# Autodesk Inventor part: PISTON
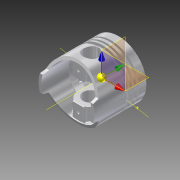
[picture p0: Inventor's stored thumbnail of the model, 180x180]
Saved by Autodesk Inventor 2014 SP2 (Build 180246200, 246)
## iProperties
Created: 2015-07
Part Number: PISTON
Material: Aluminio 6061
Document SubType Name: Modeling
Designer: Jaime
Density: 2.96864 g/cm^3
Appearance: Mecanizado - Aluminio
Mass: 440.2 g
Surface Area: 463.096 cm^2
Volume: 148.283 cm^3
Author: Jaime
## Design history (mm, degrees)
node "Plano_Lim_Superior"
sketch "Boceto3"
  geometry: L1 (40, 0)-(40, 47.7); L2 (40, 47.7)-(36.3, 47.7); L3 (36.3, 47.7)-(36.3, 51.7); L4 (36.3, 51.7)-(40, 51.7); L5 (40, 51.7)-(40, 54.7); L6 (40, 54.7)-(36.3, 54.7); L7 (36.3, 54.7)-(36.3, 57.3); L8 (36.3, 57.3)-(40, 57.3); L9 (40, 57.3)-(40, 61.3); L10 (40, 61.3)-(36.3, 61.3); L11 (36.3, 61.3)-(36.3, 63.9); L12 (36.3, 63.9)-(40, 63.9); L13 (40, 63.9)-(40, 75); L14 (40, 75)-(0, 75); L15 (40, 0)-(36.2, 0); L16 (36.2, 0)-(36.2, 36.066); L17 (36.2, 36.066)-(36.2, 39.023); L18 (35.97, 39.954)-(31.331, 48.769); L19 (31.101, 49.7)-(31.101, 54.5); L20 (29.101, 56.5)-(0, 56.5); L21 (0, 56.5)-(0, 75); L22 (0, -15)-(0, 90) reference; A1 r 2 centre (34.2, 39.023) between (36.2, 39.023) and (35.97, 39.954); A2 r 2 centre (33.101, 49.7) between (31.101, 49.7) and (31.331, 48.769); A3 r 2 centre (29.101, 54.5) between (31.101, 54.5) and (29.101, 56.5); 1 further point
  constraints: 42 end point, 10 parallel, 6 point on circle, 6 tangent, 4 collinear, 3 centre point, 2 equal radius, 2 perpendicular, 1 point on line, 1 vertical
  dimensions: "d9" = 40 distance of L1.start point (0, 0) (= 0.5 x D_Piston); "d11" = 11.1 distance of L12.end L13.end; "d12" = 3.7 distance of L11.end L12.end; "d13" = 2.6 distance of L10.end L11.end; "d14" = 4 distance of L8.end L9.end; "d15" = 3.7 distance of L7.end L8.end; "d16" = 2.6 distance of L6.end L7.end; "d17" = 3 distance of L4.end L5.end; "d18" = 4 distance of L2.end L3.end; "d19" = 40 distance of L13.end L14.end (= 0.5 x D_Piston); "d29" = 3.8 distance of L1.start L15.end; "d30" = 56.5 distance between parallel lines of L20 L15; "d31" = 75 distance between parallel lines of L15 L14 (= H_Piston); "d32" = 2 radius of A1; "d52" = 3.7 distance of L1.end L2.end
revolve "Revolución2" sketch "Boceto3" stored, may be unused: angle "d33" = 90 deg
node "Eje de trabajo1"
node "Plano de trabajo3"
sketch "Boceto5"
  geometry: L1 (16.75, 56.5)-(16.75, 16.6); L2 (16.75, 16.6)-(-16.75, 16.6); L3 (-16.75, 16.6)-(-16.75, 56.5); L4 (-36.2, 0)-(36.2, 0) reference; L5 (0, 83.843)-(0, -43.45); L6 (-16.75, 56.5)-(16.75, 56.5); 1 further point
  constraints: 10 end point, 4 perpendicular, 1 vertical, 1 other
  dimensions: "d44" = 16.6 distance between parallel lines of L2 L4; "d45" = 33.5 distance between parallel lines of L3 L1
extrude "Extrusión2" join sketch "Boceto5" stored distance "d50" = 10; taper "d51" = 0 deg
fillet "Empalme1"
mirror "Simetría1"
node "Plano de trabajo4"
sketch "Boceto6"
  geometry: L1 (-8.66, -15.2)-(8.44, -15.2); L2 (8.44, -15.2)-(8.44, -35.202); L3 (-8.66, -35.149)-(-8.66, -15.2); L4 (-0.11, -61.667)-(-0.11, -50.594); L5 (16.75, -15.2)-(-16.75, -15.2) reference; C1 r 40 at (0, 0) reference; A1 r 36.2 centre (0, 0) between (8.44, -35.202) and (-8.66, -35.149) reference; A2 r 36.2 centre (0, 0) between (-8.66, -35.149) and (8.44, -35.202); 1 further point
  constraints: 8 end point, 4 point on circle, 2 parallel, 1 centre point, 1 concentric, 1 horizontal, 1 perpendicular, 1 other
  dimensions: "d54" = 17.1 distance of L1.start L1.end; "d66" = 0 distance between parallel lines of L1 L5
extrude "Extrusión3" join sketch "Boceto6" distance "d55" = 10; taper "d56" = 0 deg
mirror "Simetría2"
node "Plano de trabajo5"
sketch "Boceto7"
  geometry: C1 r 11 at (0, 34.8); 1 further point
  constraints: 1 centre point
  dimensions: "d68" = 22 diameter of C1
hole "Hole3" sketch "Boceto7" at (0, 34.8) diameter "d69" = 22; stored, may be unused: countersink angle "d73" = 90 deg, drill point angle "d75" = 118 deg; dims "d70" = 6, "d71" = 4, "d72" = 2, "d74" = 8
sketch "Boceto10"
  geometry: L1 (16.5, 40)-(0, 40); L2 (0, 40)-(0, 12); L3 (0, 12)-(7, 13.455); L4 (8.499, 14.808)-(16.5, 40); A1 r 2 centre (6.593, 15.413) between (7, 13.455) and (8.499, 14.808); 1 further point
  constraints: 8 end point, 2 point on circle, 2 tangent, 1 centre point
  dimensions: "d77" = 12 distance of L2.end point (0, 0); "d78" = 40 distance from line of point (0, 0) L1; "d83" = 2 radius of A1; "d129" = 7 distance from line of L2 L3.end; "d130" = 16.5 distance of L1.start L1.end
extrude "Extrusión4" cut sketch "Boceto10" stored distance "d80" = 10; taper "d81" = 0 deg
mirror "Simetría3"
sketch "Boceto11"
  geometry: C1 r 2 at (0, -26)
  constraints: 1 centre point
  dimensions: "d85" = 4 diameter of C1
hole "Hole4" sketch "Boceto11" at (0, -26) diameter "d86" = 4; stored, may be unused: countersink angle "d90" = 90 deg, drill point angle "d92" = 118 deg; dims "d87" = 6, "d88" = 4, "d89" = 2, "d91" = 20
mirror "Simetría4"
chamfer "Chaflán3" distance "d93" = 0.5; stored, may be unused: second distance "d94" = 1, angle "d95" = 45 deg
chamfer "Chaflán4" distance "d96" = 1; stored, may be unused: second distance "d97" = 0.5, angle "d98" = 45 deg
sketch "Boceto13"
  geometry: L1 (75, -25.4)-(65.533, -25.4); L2 (74.5, -40)-(63.9, -40) reference; L3 (75, 39.5)-(75, -39.5) reference; L4 (69.6, -4.4)-(69.6, -3.4); L5 (69.6, -3.4)-(75, -3.4); L6 (65.936, -3.4)-(115.954, -3.4); A1 r 30 centre (92.475, -24.173) between (69.37, -5.038) and (62.54, -22.203); A2 r 3 centre (65.533, -22.4) between (62.54, -22.203) and (65.533, -25.4); A3 r 1 centre (68.6, -4.4) between (69.37, -5.038) and (69.6, -4.4); 3 further points
  constraints: 8 end point, 8 point on circle, 4 point on line, 4 tangent, 3 centre point, 1 collinear, 1 horizontal, 1 parallel, 1 perpendicular
  dimensions: "d102" = 14.6 distance between parallel lines of L2 L1; "d103" = 12.5 distance of L1.start point (62.5, -25.4); "d104" = 3 radius of A2; "d105" = 30 radius of A1; "d106" = 1 radius of A3; "d107" = 22 distance from line of L1 L5.end; "d108" = 5.4 distance between parallel lines of L3 L4; "d109" = 1 distance of L4.start L4.end
node "Eje de trabajo2"
revolve "Revolución3" stored, may be unused: angle "d110" = 90 deg
fillet "Empalme2" dims "d111" = 0.5
fillet "Empalme3" dims "d112" = 1
sketch "Boceto14"
  geometry: L1 (0, 0)-(53.226, 9.385); L2 (0, 0)-(54.047, 0); C1 r 36.3 at (0, 0) reference; C2 r 39.5 at (0, 0) reference; 1 further point
  constraints: 4 end point, 1 coincident, 1 equal length, 1 horizontal
  dimensions: "d113" = 10 deg angle of L2 L1
node "Punto de trabajo1"
node "Eje de trabajo3"
hole "Hole5" diameter "d116" = 3.7; stored, may be unused: countersink angle "d120" = 90 deg, drill point angle "d122" = 118 deg; dims "d114" = 10, "d115" = 10, "d117" = 6, "d118" = 4, "d119" = 2, "d121" = 8
pattern_circular "Patrón circular1" dims angle "d124" = 40 deg
pattern_circular "Patrón circular2" dims angle "d127" = 20 deg
node "Sólido3"
node "Proyectar aristas de corte2"
other parameters: "H_Piston" = 75 [user parameter; used in 2 equation terms], "D_Aguje" = 3.7 [user parameter], "d2" = 75 (= H_Piston), "d43" = 15.2, "d53" = -58.5, "d67" = 45.75
